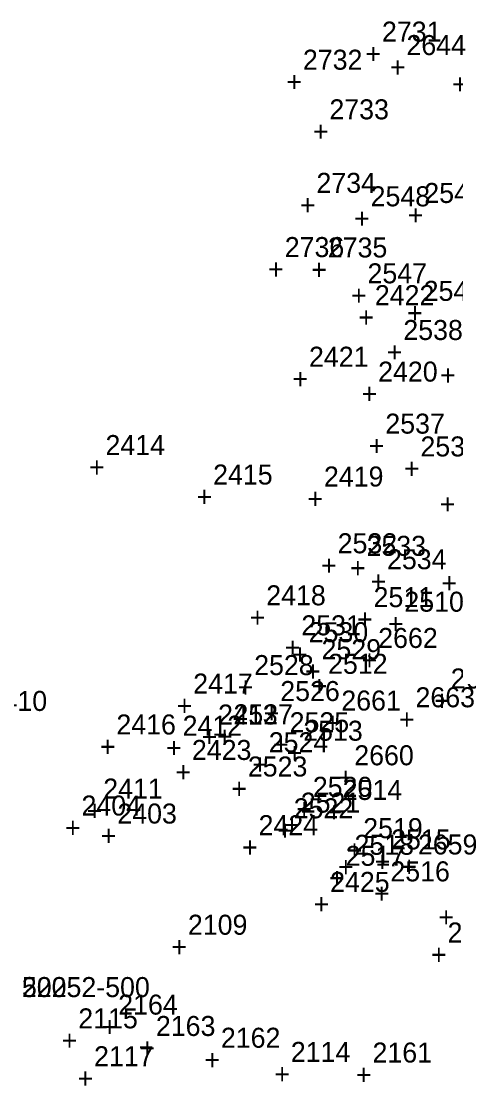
# Model space of a CAD drawing. Extents: x 2192192 to 2193475, y 863716 to 864270.
# Drawn here: x 2192587.2 to 2192641.5, y 863942.7 to 864075.7 of the extents above; entities that cross this region are included whole.
import ezdxf

# ---------------------------------------------------------------- set-up
doc = ezdxf.new("R2010")
doc.units = 0
for name, color, linetype in [('S_Control_Geodetic_ControlPoint', 7, 'Continuous'), ('S_Drainage_Ditch_Line', 7, 'Continuous'), ('S_Drainage_Waterway', 7, 'Continuous'), ('S_Ground_Elevation', 7, 'Continuous'), ('S_Ground_LevelString', 7, 'Continuous'), ('S_Ground_SpotElevation', 7, 'Continuous'), ('S_Guardrail_Beam', 7, 'Continuous'), ('S_Roadway_Edge_Pavement', 7, 'Continuous'), ('S_Roadway_Edge_TW', 7, 'Continuous'), ('S_Trees_TreeLine', 7, 'Continuous')]:
    doc.layers.add(name, color=color, linetype=linetype)

msp = doc.modelspace()

# ---------------------------------------------------------------- texts
at = {"layer": 'S_Control_Geodetic_ControlPoint'}
for s in ['500', '500', '500', '500', '500', '500', '500', '500', '22252-500']:
    msp.add_text(s, height=2.5, dxfattribs=at).set_placement((2192587.25, 863953.79))
at = {"layer": 'S_Drainage_Ditch_Line'}
for s, p in [('2410', (2192582.97, 863989.54)), ('2413', (2192611.77, 863987.84)), ('2412', (2192607.34, 863986.45)), ('+', (2192609.71, 863985.09)), ('+', (2192605.28, 863983.7)), ('2411', (2192597.42, 863978.59)), ('+', (2192595.36, 863975.84))]:
    msp.add_text(s, height=2.5, dxfattribs=at).set_placement(p)
at = {"layer": 'S_Drainage_Waterway'}
for s, p in [('2644', (2192635.31, 864071.49)), ('+', (2192633.25, 864068.74)), ('2548', (2192630.83, 864052.59)), ('2549', (2192637.54, 864053.01)), ('+', (2192628.77, 864049.84)), ('+', (2192635.48, 864050.26)), ('2547', (2192630.44, 864042.97)), ('2546', (2192637.46, 864040.78)), ('+', (2192628.38, 864040.22)), ('+', (2192635.4, 864038.03)), ('2538', (2192634.92, 864035.89)), ('+', (2192632.86, 864033.14)), ('2537', (2192632.67, 864024.19)), ('+', (2192630.6, 864021.44)), ('2532', (2192626.71, 864009.24)), ('+', (2192624.64, 864006.49)), ('+', (2192639.68, 864004.29)), ('2511', (2192631.2, 864002.51)), ('2510', (2192635.05, 864001.94)), ('2531', (2192622.17, 863998.99)), ('+', (2192629.14, 863999.76)), ('+', (2192632.99, 863999.19)), ('+', (2192620.11, 863996.24)), ('2512', (2192625.51, 863994.18)), ('2528', (2192616.28, 863994.02)), ('+', (2192614.22, 863991.27)), ('+', (2192623.45, 863991.43)), ('2527', (2192613.69, 863987.87)), ('2513', (2192622.41, 863985.82)), ('+', (2192611.63, 863985.12)), ('+', (2192620.35, 863983.07)), ('2523', (2192615.49, 863981.35)), ('+', (2192613.43, 863978.6)), ('2514', (2192627.34, 863978.42)), ('2522', (2192621.22, 863976.13)), ('+', (2192625.28, 863975.67)), ('+', (2192619.16, 863973.38)), ('2515', (2192633.39, 863972.24)), ('2517', (2192627.71, 863970.19)), ('+', (2192631.33, 863969.49)), ('2516', (2192633.3, 863968.25)), ('+', (2192625.65, 863967.44)), ('+', (2192631.24, 863965.5))]:
    msp.add_text(s, height=2.5, dxfattribs=at).set_placement(p)
at = {"layer": 'S_Ground_Elevation'}
for s, p in [('2731', (2192632.25, 864073.17)), ('+', (2192630.19, 864070.42)), ('2732', (2192622.37, 864069.66)), ('+', (2192620.31, 864066.91)), ('2733', (2192625.68, 864063.46)), ('+', (2192623.62, 864060.71)), ('2734', (2192624.06, 864054.27)), ('+', (2192622, 864051.52)), ('2736', (2192620.1, 864046.25)), ('2735', (2192625.48, 864046.2)), ('+', (2192618.03, 864043.5)), ('+', (2192623.41, 864043.45)), ('2422', (2192631.36, 864040.24)), ('+', (2192629.3, 864037.49)), ('2420', (2192631.77, 864030.69)), ('+', (2192629.71, 864027.94)), ('2414', (2192597.7, 864021.51)), ('+', (2192595.64, 864018.76)), ('2419', (2192625, 864017.58)), ('+', (2192622.94, 864014.83)), ('2418', (2192617.79, 864002.74)), ('+', (2192615.72, 863999.99)), ('2662', (2192631.78, 863997.41)), ('+', (2192629.72, 863994.66)), ('2417', (2192608.66, 863991.71)), ('2664', (2192640.84, 863992.35)), ('2661', (2192627.17, 863989.59)), ('2663', (2192636.44, 863990)), ('+', (2192638.78, 863989.6)), ('+', (2192606.6, 863988.96)), ('2416', (2192599.06, 863986.6)), ('+', (2192625.1, 863986.84)), ('+', (2192634.38, 863987.25)), ('+', (2192597, 863983.85)), ('2423', (2192608.5, 863983.42)), ('2660', (2192628.79, 863982.75)), ('+', (2192606.44, 863980.67)), ('+', (2192626.73, 863980)), ('2403', (2192599.18, 863975.47)), ('2424', (2192616.83, 863974.02)), ('+', (2192597.11, 863972.72)), ('2659', (2192636.74, 863971.61)), ('+', (2192614.77, 863971.27)), ('+', (2192634.67, 863968.86)), ('2425', (2192625.77, 863966.93)), ('+', (2192623.71, 863964.18)), ('+', (2192639.3, 863962.55)), ('2426', (2192640.45, 863960.61)), ('+', (2192638.38, 863957.86))]:
    msp.add_text(s, height=2.5, dxfattribs=at).set_placement(p)
at = {"layer": 'S_Ground_LevelString'}
for s, p in [('2115', (2192594.3, 863949.88)), ('+', (2192592.23, 863947.13)), ('2114', (2192620.86, 863945.69)), ('+', (2192618.8, 863942.94))]:
    msp.add_text(s, height=2.5, dxfattribs=at).set_placement(p)
at = {"layer": 'S_Ground_SpotElevation'}
for s, p in [('+', (2192641.02, 864066.63)), ('2421', (2192623.13, 864032.55)), ('+', (2192621.07, 864029.8)), ('+', (2192639.51, 864030.25)), ('2536', (2192637.06, 864021.34)), ('+', (2192635, 864018.59)), ('+', (2192639.48, 864014.15)), ('2533', (2192630.32, 864008.92)), ('2534', (2192632.88, 864007.25)), ('+', (2192628.26, 864006.17)), ('+', (2192630.82, 864004.5)), ('2530', (2192623.09, 863998.13)), ('2529', (2192624.7, 863996.01)), ('+', (2192621.02, 863995.38)), ('+', (2192622.64, 863993.26)), ('2526', (2192619.54, 863990.78)), ('+', (2192617.48, 863988.03)), ('2525', (2192620.71, 863986.88)), ('2524', (2192618.1, 863984.38)), ('+', (2192618.65, 863984.13)), ('+', (2192616.04, 863981.63)), ('2520', (2192623.61, 863978.81)), ('2521', (2192622.1, 863976.84)), ('+', (2192621.55, 863976.06)), ('+', (2192620.04, 863974.09)), ('2519', (2192629.91, 863973.65)), ('2518', (2192628.82, 863971.57)), ('+', (2192627.84, 863970.9)), ('+', (2192626.76, 863968.82))]:
    msp.add_text(s, height=2.5, dxfattribs=at).set_placement(p)
at = {"layer": 'S_Guardrail_Beam'}
for s, p in [('2164', (2192599.29, 863951.6)), ('2163', (2192604, 863948.93)), ('+', (2192597.23, 863948.85)), ('2162', (2192612.12, 863947.46)), ('+', (2192601.94, 863946.18)), ('2161', (2192631.07, 863945.61)), ('+', (2192610.06, 863944.71)), ('+', (2192629, 863942.86))]:
    msp.add_text(s, height=2.5, dxfattribs=at).set_placement(p)
at = {"layer": 'S_Roadway_Edge_Pavement'}
for s, p in [('2109', (2192608, 863961.58)), ('+', (2192605.94, 863958.83))]:
    msp.add_text(s, height=2.5, dxfattribs=at).set_placement(p)
at = {"layer": 'S_Roadway_Edge_TW'}
for s, p in [('2117', (2192596.27, 863945.15)), ('+', (2192594.21, 863942.4))]:
    msp.add_text(s, height=2.5, dxfattribs=at).set_placement(p)
at = {"layer": 'S_Trees_TreeLine'}
for s, p in [('2415', (2192611.15, 864017.83)), ('+', (2192609.09, 864015.08)), ('2404', (2192594.7, 863976.47)), ('+', (2192592.64, 863973.72))]:
    msp.add_text(s, height=2.5, dxfattribs=at).set_placement(p)

doc.saveas('drawing.dxf')
